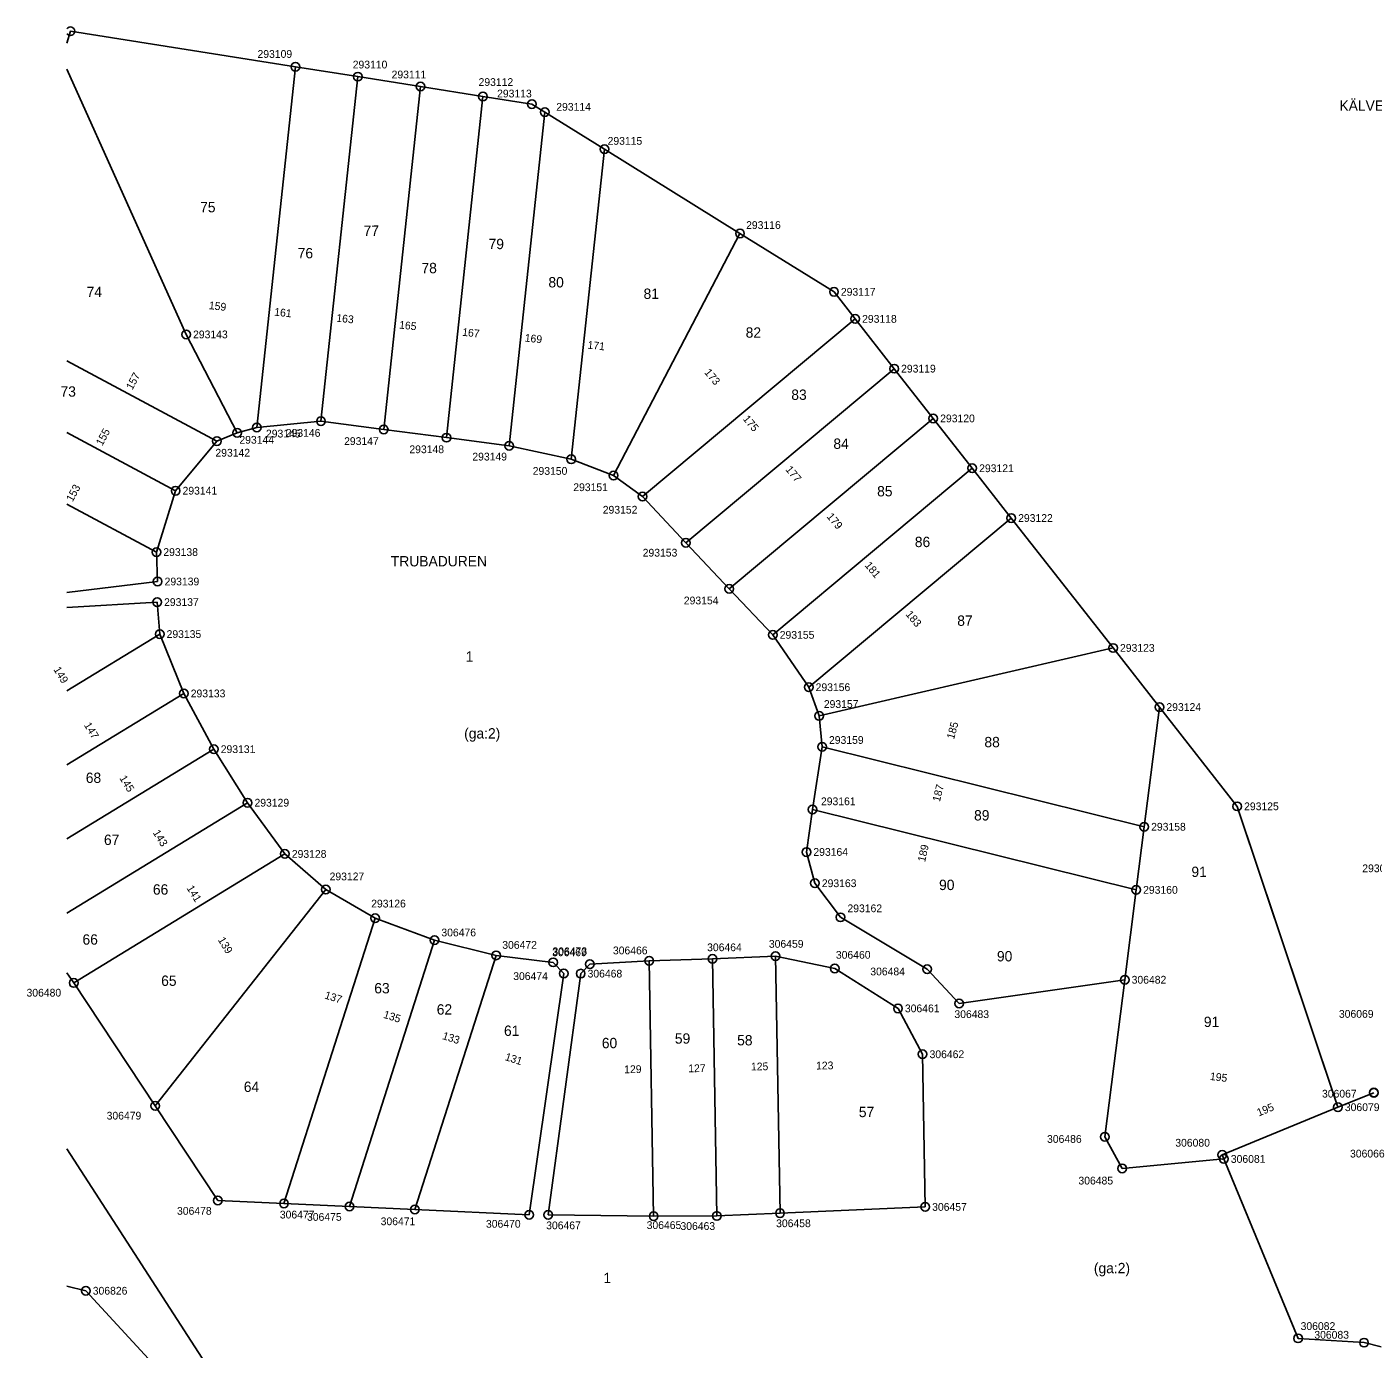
# Model space of a CAD drawing. Extents: x 141995 to 152570, y 6580184 to 6586000.
# Drawn here: x 141995.4 to 142151.4, y 6585594.9 to 6585748.2 of the extents above; entities that cross this region are included whole.
import ezdxf

# ---------------------------------------------------------------- set-up
doc = ezdxf.new("R2010")
doc.units = 0
for name, color, linetype in [('Level 10', 7, 'Continuous'), ('Level 13', 7, 'Continuous'), ('Level 5', 7, 'Continuous'), ('Level 50', 7, 'Continuous'), ('Level 51', 7, 'Continuous'), ('Level 53', 7, 'Continuous'), ('Level 54', 7, 'Continuous'), ('Level 55', 7, 'Continuous'), ('Level 56', 7, 'Continuous'), ('Level 59', 7, 'Continuous'), ('Level 6', 7, 'Continuous'), ('Level 7', 7, 'Continuous')]:
    doc.layers.add(name, color=color, linetype=linetype)

msp = doc.modelspace()

# ---------------------------------------------------------------- linework, layer by layer
at = {"layer": 'Level 10'}
for centre in [(142026.49, 6585743.62), (142033.74, 6585742.47), (142040.99, 6585741.33), (142048.24, 6585740.18), (142053.92, 6585739.29), (142055.42, 6585738.36), (142062.33, 6585734.06), (142078.04, 6585724.29), (142088.94, 6585717.52), (142091.4, 6585714.38), (142013.83, 6585712.58), (142095.92, 6585708.61), (142029.46, 6585702.51), (142100.45, 6585702.84), (142019.74, 6585701.17), (142022.01, 6585701.8), (142036.73, 6585701.56), (142044, 6585700.61), (142017.4, 6585700.21), (142051.27, 6585699.67), (142058.48, 6585698.1), (142063.39, 6585696.21), (142104.97, 6585697.06), (142012.61, 6585694.46), (142066.74, 6585693.78), (142109.49, 6585691.29), (142071.77, 6585688.43), (142010.38, 6585687.33), (142010.52, 6585683.93), (142076.8, 6585683.08), (142010.47, 6585681.54), (142010.76, 6585677.83), (142081.84, 6585677.74), (142121.3, 6585676.22), (142013.56, 6585670.95), (142086.01, 6585671.67), (142126.68, 6585669.37), (142087.21, 6585668.34), (142017.04, 6585664.48), (142087.56, 6585664.77), (142020.95, 6585658.28), (142086.46, 6585657.49), (142135.69, 6585657.86), (142124.91, 6585655.49), (142025.28, 6585652.34), (142085.75, 6585652.56), (142086.73, 6585648.94), (142030.02, 6585648.21), (142123.98, 6585648.17), (142035.74, 6585644.88), (142089.7, 6585644.99), (142042.63, 6585642.35), (142049.76, 6585640.58), (142056.38, 6585639.77), (142060.63, 6585639.57), (142067.52, 6585639.95), (142074.85, 6585640.17), (142082.17, 6585640.49), (142057.6, 6585638.49), (142059.57, 6585638.46), (142089.02, 6585639.06), (142099.75, 6585638.97), (142000.79, 6585637.38), (142122.65, 6585637.75), (142103.44, 6585635.01), (142096.36, 6585634.43), (142099.21, 6585629.11), (142151.52, 6585624.68), (142151.54, 6585624.63), (142010.24, 6585623.12), (142147.37, 6585622.97), (142120.34, 6585619.54), (142133.96, 6585617.44), (142134.15, 6585616.97), (142122.34, 6585615.88), (142017.5, 6585612.16), (142025.17, 6585611.81), (142032.76, 6585611.46), (142099.52, 6585611.41), (142040.34, 6585611.11), (142053.61, 6585610.5), (142055.81, 6585610.48), (142068.03, 6585610.34), (142075.36, 6585610.36), (142082.68, 6585610.68), (142002.2, 6585601.69), (142142.74, 6585596.17), (142150.39, 6585595.67)]:
    msp.add_circle(centre, 0.5, dxfattribs=at)
msp.add_arc((142000.41, 6585747.74), 0.5, 214.8629, 145.1371, dxfattribs=at)
at = {"layer": 'Level 13'}
msp.add_lwpolyline([(142147.37, 6585622.97), (142151.54, 6585624.63)], dxfattribs=at)
at = {"layer": 'Level 5'}
for points in [[(142000, 6585746.36), (142000.41, 6585747.74)], [(142000.41, 6585747.74), (142026.49, 6585743.62)], [(142026.49, 6585743.62), (142033.74, 6585742.47)], [(142033.74, 6585742.47), (142040.99, 6585741.33)], [(142040.99, 6585741.33), (142048.24, 6585740.18)], [(142048.24, 6585740.18), (142053.92, 6585739.29)], [(142053.92, 6585739.29), (142055.42, 6585738.36)], [(142055.42, 6585738.36), (142062.33, 6585734.06)], [(142062.33, 6585734.06), (142078.04, 6585724.29)], [(142078.04, 6585724.29), (142088.94, 6585717.52)], [(142088.94, 6585717.52), (142091.4, 6585714.38)], [(142091.4, 6585714.38), (142095.92, 6585708.61)], [(142095.92, 6585708.61), (142100.45, 6585702.84)], [(142100.45, 6585702.84), (142104.97, 6585697.06)], [(142104.97, 6585697.06), (142109.49, 6585691.29)], [(142109.49, 6585691.29), (142121.3, 6585676.22)], [(142121.3, 6585676.22), (142126.68, 6585669.37)], [(142126.68, 6585669.37), (142135.69, 6585657.86)], [(142135.69, 6585657.86), (142147.37, 6585622.97)], [(142147.37, 6585622.97), (142133.96, 6585617.44)], [(142133.96, 6585617.44), (142134.15, 6585616.97)], [(142142.74, 6585596.17), (142134.15, 6585616.97)], [(142150.39, 6585595.67), (142142.74, 6585596.17)], [(142152.36, 6585595.2), (142150.39, 6585595.67)]]:
    msp.add_lwpolyline(points, dxfattribs=at)
at = {"layer": 'Level 6'}
msp.add_lwpolyline([(142152.36, 6585595.2), (142150.39, 6585595.67), (142142.74, 6585596.17), (142134.15, 6585616.97), (142133.96, 6585617.44), (142147.37, 6585622.97), (142140.21, 6585644.36), (142135.69, 6585657.86), (142126.68, 6585669.37), (142121.3, 6585676.22), (142109.49, 6585691.29), (142104.97, 6585697.06), (142100.45, 6585702.84), (142095.92, 6585708.61), (142091.4, 6585714.38), (142088.94, 6585717.52), (142078.04, 6585724.29), (142062.33, 6585734.06), (142055.42, 6585738.36), (142053.92, 6585739.29), (142048.24, 6585740.18), (142040.99, 6585741.33), (142033.74, 6585742.47), (142026.49, 6585743.62), (142000.41, 6585747.74), (142000, 6585746.36)], dxfattribs=at)
at = {"layer": 'Level 7'}
for points in [[(142000, 6585743.32), (142013.83, 6585712.58)], [(142026.49, 6585743.62), (142022.01, 6585701.8)], [(142033.74, 6585742.47), (142029.46, 6585702.51)], [(142040.99, 6585741.33), (142036.73, 6585701.56)], [(142048.24, 6585740.18), (142044, 6585700.61)], [(142055.42, 6585738.36), (142051.27, 6585699.67)], [(142062.33, 6585734.06), (142058.48, 6585698.1)], [(142078.04, 6585724.29), (142063.39, 6585696.21)], [(142091.4, 6585714.38), (142066.74, 6585693.78)], [(142013.83, 6585712.58), (142019.74, 6585701.17)], [(142000, 6585709.52), (142017.4, 6585700.21)], [(142095.92, 6585708.61), (142071.77, 6585688.43)], [(142029.46, 6585702.51), (142022.01, 6585701.8)], [(142036.73, 6585701.56), (142029.46, 6585702.51)], [(142100.45, 6585702.84), (142076.8, 6585683.08)], [(142000, 6585701.21), (142012.61, 6585694.46)], [(142019.74, 6585701.17), (142017.4, 6585700.21)], [(142022.01, 6585701.8), (142019.74, 6585701.17)], [(142044, 6585700.61), (142036.73, 6585701.56)], [(142017.4, 6585700.21), (142012.61, 6585694.46)], [(142051.27, 6585699.67), (142044, 6585700.61)], [(142058.48, 6585698.1), (142051.27, 6585699.67)], [(142063.39, 6585696.21), (142058.48, 6585698.1)], [(142066.74, 6585693.78), (142063.39, 6585696.21)], [(142104.97, 6585697.06), (142081.84, 6585677.74)], [(142012.61, 6585694.46), (142010.38, 6585687.33)], [(142071.77, 6585688.43), (142066.74, 6585693.78)], [(142000, 6585692.89), (142010.38, 6585687.33)], [(142109.49, 6585691.29), (142086.01, 6585671.67)], [(142076.8, 6585683.08), (142071.77, 6585688.43)], [(142010.38, 6585687.33), (142010.52, 6585683.93)], [(142010.52, 6585683.93), (142000, 6585682.65)], [(142081.84, 6585677.74), (142076.8, 6585683.08)], [(142000, 6585680.92), (142010.47, 6585681.54)], [(142010.47, 6585681.54), (142010.76, 6585677.83)], [(142000, 6585671.26), (142010.76, 6585677.83)], [(142010.76, 6585677.83), (142013.56, 6585670.95)], [(142086.01, 6585671.67), (142081.84, 6585677.74)], [(142121.3, 6585676.22), (142087.21, 6585668.34)], [(142087.21, 6585668.34), (142086.01, 6585671.67)], [(142000, 6585662.67), (142013.56, 6585670.95)], [(142013.56, 6585670.95), (142017.04, 6585664.48)], [(142087.56, 6585664.77), (142087.21, 6585668.34)], [(142124.91, 6585655.49), (142126.68, 6585669.37)], [(142000, 6585654.08), (142017.04, 6585664.48)], [(142017.04, 6585664.48), (142020.95, 6585658.28)], [(142086.46, 6585657.49), (142087.56, 6585664.77)], [(142124.91, 6585655.49), (142087.56, 6585664.77)], [(142000, 6585645.49), (142020.95, 6585658.28)], [(142020.95, 6585658.28), (142025.28, 6585652.34)], [(142085.75, 6585652.56), (142086.46, 6585657.49)], [(142086.46, 6585657.49), (142123.98, 6585648.17)], [(142123.98, 6585648.17), (142124.91, 6585655.49)], [(142086.73, 6585648.94), (142085.75, 6585652.56)], [(142025.28, 6585652.34), (142000.79, 6585637.38)], [(142025.28, 6585652.34), (142030.02, 6585648.21)], [(142030.02, 6585648.21), (142010.24, 6585623.12)], [(142030.02, 6585648.21), (142035.74, 6585644.88)], [(142089.7, 6585644.99), (142086.73, 6585648.94)], [(142123.98, 6585648.17), (142122.65, 6585637.75)], [(142035.74, 6585644.88), (142025.17, 6585611.81)], [(142035.74, 6585644.88), (142037.4, 6585644.27)], [(142089.7, 6585644.99), (142099.75, 6585638.97)], [(142037.4, 6585644.27), (142042.63, 6585642.35)], [(142042.63, 6585642.35), (142032.76, 6585611.46)], [(142042.63, 6585642.35), (142049.76, 6585640.58)], [(142040.34, 6585611.11), (142049.76, 6585640.58)], [(142049.76, 6585640.58), (142056.38, 6585639.77)], [(142060.63, 6585639.57), (142067.52, 6585639.95)], [(142067.52, 6585639.95), (142074.85, 6585640.17)], [(142068.03, 6585610.34), (142067.52, 6585639.95)], [(142074.85, 6585640.17), (142082.17, 6585640.49)], [(142075.36, 6585610.36), (142074.85, 6585640.17)], [(142082.17, 6585640.49), (142089.02, 6585639.06)], [(142082.68, 6585610.68), (142082.17, 6585640.49)], [(142000.79, 6585637.38), (142000, 6585638.57)], [(142057.6, 6585638.49), (142053.61, 6585610.5)], [(142055.81, 6585610.48), (142059.57, 6585638.46)], [(142056.38, 6585639.77), (142057.6, 6585638.49)], [(142059.57, 6585638.46), (142060.63, 6585639.57)], [(142089.02, 6585639.06), (142096.36, 6585634.43)], [(142103.44, 6585635.01), (142099.75, 6585638.97)], [(142010.24, 6585623.12), (142000.79, 6585637.38)], [(142122.65, 6585637.75), (142103.44, 6585635.01)], [(142120.34, 6585619.54), (142122.65, 6585637.75)], [(142096.36, 6585634.43), (142099.21, 6585629.11)], [(142099.21, 6585629.11), (142099.52, 6585611.41)], [(142017.5, 6585612.16), (142010.24, 6585623.12)], [(142000, 6585618.14), (142039.14, 6585557.56)], [(142122.34, 6585615.88), (142120.34, 6585619.54)], [(142134.15, 6585616.97), (142122.34, 6585615.88)], [(142025.17, 6585611.81), (142017.5, 6585612.16)], [(142032.76, 6585611.46), (142025.17, 6585611.81)], [(142040.34, 6585611.11), (142032.76, 6585611.46)], [(142053.61, 6585610.5), (142040.34, 6585611.11)], [(142068.03, 6585610.34), (142055.81, 6585610.48)], [(142075.36, 6585610.36), (142068.03, 6585610.34)], [(142082.68, 6585610.68), (142075.36, 6585610.36)], [(142099.52, 6585611.41), (142082.68, 6585610.68)], [(142000, 6585602.24), (142002.2, 6585601.69)], [(142002.2, 6585601.69), (142011.29, 6585591.81)]]:
    msp.add_lwpolyline(points, dxfattribs=at)

# ---------------------------------------------------------------- texts
at = {"layer": 'Level 50'}
msp.add_text('TRUBADUREN', height=1.2, rotation=0.0527, dxfattribs=at).set_placement((142037.56, 6585685.68))
at = {"layer": 'Level 51'}
for s, p in [('75', (142015.45, 6585726.74)), ('77', (142034.4, 6585724.01)), ('76', (142026.76, 6585721.4)), ('79', (142048.89, 6585722.47)), ('78', (142041.11, 6585719.68)), ('74', (142002.29, 6585716.91)), ('80', (142055.83, 6585718.03)), ('81', (142066.86, 6585716.7)), ('82', (142078.7, 6585712.2)), ('73', (141999.26, 6585705.36)), ('83', (142083.99, 6585704.99)), ('84', (142088.87, 6585699.31)), ('85', (142093.94, 6585693.8)), ('86', (142098.31, 6585687.92)), ('87', (142103.23, 6585678.79)), ('1', (142046.24, 6585674.63)), ('(ga:2)', (142046.06, 6585665.72)), ('88', (142106.38, 6585664.71)), ('68', (142002.19, 6585660.57)), ('89', (142105.18, 6585656.22)), ('67', (142004.3, 6585653.38)), ('90', (142101.12, 6585648.15)), ('66', (142009.97, 6585647.62)), ('65', (142010.93, 6585637.04)), ('63', (142035.64, 6585636.17)), ('62', (142042.88, 6585633.71)), ('61', (142050.68, 6585631.24)), ('91', (142131.82, 6585632.27)), ('60', (142062.02, 6585629.81)), ('59', (142070.49, 6585630.34)), ('58', (142077.71, 6585630.14)), ('64', (142020.51, 6585624.74)), ('57', (142091.82, 6585621.82)), ('1', (142062.21, 6585602.58))]:
    msp.add_text(s, height=1.2, rotation=0.0527, dxfattribs=at).set_placement(p)
msp.add_text('(ga:2)', height=1.2, dxfattribs=at).set_placement((142119.07, 6585603.72))
at = {"layer": 'Level 53'}
for s, p in [('293109', (142022.1, 6585744.65)), ('293110', (142033.14, 6585743.42)), ('293111', (142037.65, 6585742.27)), ('293112', (142047.73, 6585741.39)), ('293113', (142049.88, 6585740.06)), ('293114', (142056.74, 6585738.52)), ('293115', (142062.69, 6585734.57)), ('293116', (142078.75, 6585724.81)), ('293117', (142089.74, 6585717.07)), ('293118', (142092.2, 6585713.93)), ('293143', (142014.63, 6585712.13)), ('293119', (142096.72, 6585708.16)), ('293120', (142101.25, 6585702.39)), ('293144', (142020, 6585699.91)), ('293145', (142023.08, 6585700.63)), ('293146', (142025.38, 6585700.71)), ('293142', (142017.22, 6585698.41)), ('293147', (142032.14, 6585699.76)), ('293148', (142039.71, 6585698.81)), ('293149', (142047.01, 6585697.96)), ('293150', (142054.01, 6585696.3)), ('293121', (142105.77, 6585696.61)), ('293141', (142013.41, 6585694.01)), ('293151', (142058.71, 6585694.41)), ('293152', (142062.13, 6585691.8)), ('293122', (142110.29, 6585690.84)), ('293138', (142011.18, 6585686.89)), ('293153', (142066.76, 6585686.82)), ('293139', (142011.33, 6585683.48)), ('293154', (142071.53, 6585681.28)), ('293137', (142011.27, 6585681.09)), ('293135', (142011.56, 6585677.38)), ('293155', (142082.65, 6585677.29)), ('293123', (142122.1, 6585675.78)), ('293133', (142014.36, 6585670.5)), ('293156', (142086.81, 6585671.22)), ('293157', (142087.76, 6585669.27)), ('293124', (142127.48, 6585668.92)), ('293131', (142017.84, 6585664.04)), ('293159', (142088.36, 6585665.1)), ('293129', (142021.75, 6585657.83)), ('293161', (142087.43, 6585657.99)), ('293125', (142136.49, 6585657.41)), ('293158', (142125.71, 6585655.04)), ('293128', (142026.08, 6585651.89)), ('293164', (142086.55, 6585652.12)), ('293078', (142150.19, 6585650.22)), ('293127', (142030.46, 6585649.28)), ('293163', (142087.53, 6585648.49)), ('293160', (142124.78, 6585647.72)), ('293126', (142035.28, 6585646.13)), ('293162', (142090.5, 6585645.58)), ('306476', (142043.42, 6585642.78)), ('306472', (142050.48, 6585641.34)), ('306473', (142056.3, 6585640.6)), ('306466', (142063.31, 6585640.7)), ('306464', (142074.23, 6585641.06)), ('306459', (142081.39, 6585641.46)), ('306469', (142056.26, 6585640.48)), ('306460', (142089.16, 6585640.19)), ('306474', (142051.75, 6585637.72)), ('306468', (142060.37, 6585638.01)), ('306484', (142093.15, 6585638.26)), ('306482', (142123.45, 6585637.3)), ('306480', (141995.32, 6585635.8)), ('306461', (142097.16, 6585633.98)), ('306483', (142102.9, 6585633.31)), ('306069', (142147.48, 6585633.34)), ('306462', (142100.02, 6585628.66)), ('306067', (142145.52, 6585624.09)), ('306079', (142148.17, 6585622.52)), ('306479', (142004.61, 6585621.54)), ('306486', (142113.64, 6585618.84)), ('306080', (142128.51, 6585618.4)), ('306066', (142148.77, 6585617.14)), ('306081', (142134.95, 6585616.52)), ('306485', (142117.28, 6585614.01)), ('306457', (142100.32, 6585610.96)), ('306478', (142012.77, 6585610.5)), ('306477', (142024.69, 6585610.07)), ('306475', (142027.84, 6585609.8)), ('306471', (142036.38, 6585609.29)), ('306470', (142048.59, 6585609)), ('306467', (142055.57, 6585608.82)), ('306465', (142067.22, 6585608.85)), ('306463', (142071.14, 6585608.74)), ('306458', (142082.23, 6585609.06)), ('306826', (142003, 6585601.24)), ('306082', (142143.04, 6585597.14)), ('306083', (142144.63, 6585596.13))]:
    msp.add_text(s, height=0.9, rotation=0.0527, dxfattribs=at).set_placement(p)
at = {"layer": 'Level 54'}
for s, rotation, p in [('159', 353.8937, (142016.43, 6585715.52)), ('161', 353.8937, (142024.01, 6585714.77)), ('163', 353.8937, (142031.21, 6585714.07)), ('165', 353.8937, (142038.49, 6585713.27)), ('167', 353.8937, (142045.8, 6585712.43)), ('169', 353.8937, (142053.05, 6585711.76)), ('171', 353.8937, (142060.33, 6585710.94)), ('157', 61.8039, (142007.59, 6585706.08)), ('173', 309.8982, (142073.85, 6585708.15)), ('175', 309.8982, (142078.32, 6585702.76)), ('155', 61.8039, (142004.1, 6585699.59)), ('177', 309.8982, (142083.26, 6585696.89)), ('153', 61.8039, (142000.66, 6585693.1)), ('179', 309.8982, (142088.04, 6585691.43)), ('181', 309.8982, (142092.45, 6585685.78)), ('183', 309.8982, (142097.19, 6585680.1)), ('149', 301.4789, (141998.41, 6585673.73)), ('147', 301.4789, (142001.95, 6585667.28)), ('185', 74.8095, (142102.85, 6585665.58)), ('145', 301.4789, (142006.06, 6585661.13)), ('187', 75.9795, (142101.21, 6585658.33)), ('143', 301.4789, (142009.93, 6585654.81)), ('189', 77.3904, (142099.5, 6585651.36)), ('141', 301.4789, (142013.85, 6585648.38)), ('139', 301.4759, (142017.47, 6585642.38)), ('137', 342.1974, (142029.81, 6585635.6)), ('135', 342.1974, (142036.62, 6585633.36)), ('133', 342.1974, (142043.46, 6585630.89)), ('131', 342.1974, (142050.72, 6585628.45)), ('129', 0.9427, (142064.62, 6585626.91)), ('127', 0.9427, (142072.05, 6585627.02)), ('125', 0.9427, (142079.32, 6585627.23)), ('123', 0.9427, (142086.87, 6585627.34)), ('195', 353.0007, (142132.49, 6585626.14))]:
    msp.add_text(s, height=0.9, rotation=rotation, dxfattribs=at).set_placement(p)
at = {"layer": 'Level 55'}
msp.add_text('195', height=0.9, rotation=22.4264, dxfattribs=at).set_placement((142138.19, 6585621.89))
at = {"layer": 'Level 56'}
msp.add_text('KÄLVESTA', height=1.2, rotation=0.0527, dxfattribs=at).set_placement((142147.54, 6585738.51))
at = {"layer": 'Level 59'}
for s, p in [('91', (142130.38, 6585649.67)), ('66', (142001.81, 6585641.82)), ('90', (142107.83, 6585639.88))]:
    msp.add_text(s, height=1.2, rotation=0.0527, dxfattribs=at).set_placement(p)

doc.saveas('drawing.dxf')
